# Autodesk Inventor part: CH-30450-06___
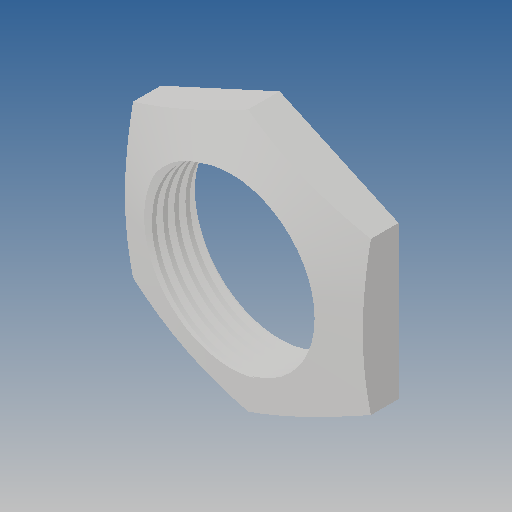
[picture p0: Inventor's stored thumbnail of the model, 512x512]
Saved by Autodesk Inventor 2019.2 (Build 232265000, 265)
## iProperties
Created: 2010-06
Part Number: CH-30450-06___
Material: Ogólny
Document SubType Name: Modeling
Designer: CADENGINEERING4
Density: 1 g/cm^3
Appearance: Domyślna
Author: CADENGINEERING4
Revision Number: ANY
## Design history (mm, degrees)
feature "NONE"
node "Bryła1"
